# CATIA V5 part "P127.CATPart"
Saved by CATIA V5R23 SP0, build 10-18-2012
Part number: P127
Definition: Axe Tendeur
Bounding box of the stored display mesh (mm): x 0 to 20, y -4 to 4, z -4 to 4
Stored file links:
  C:\wamp\www\COURS\CONCEPTION GMP1\TITRE 02-SEMESTRE 2\03-TP7-PRESSE MECANIQUE\eleve\P127.CATPart
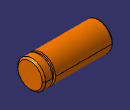
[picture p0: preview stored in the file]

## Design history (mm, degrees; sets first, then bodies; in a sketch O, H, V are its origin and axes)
Body1 (main body)
  Sketch1 on yz-plane, origin (0, 0, 0), H (0, 1, 0), V (0, 0, 1)
    circle A1 centre (0, 0) radius 4
    radius A1 = 4
  Pad1: profile Sketch1, direction (1, 0, 0), length 20
  Chamfer1: length 0.5, angle 45, on edge [face of Pad1 | face of Pad1]
  Thread1: "M8", diameter 8, depth 5, pitch 1.25, on face of Pad1, from face of Pad1
  Chamfer2: length 0.5, angle 45, on edge [face of Pad1 | face of Pad1]
  Sketch2 on zx-plane, origin (0, 0, 0), H (-1, 0, 0), V (0, 0, 1)
    line L1 (-17.5, 7.0809) -> (-16.7, 7.0809)
    line L2 (-16.7, 7.0809) -> (-16.7, 3.5)
    line L3 (-16.7, 3.5) -> (-17.5, 3.5)
    line L4 (-17.5, 3.5) -> (-17.5, 7.0809)
    reference projected line E1 (-20, -3.5) -> (-20, 3.5) from edge [face of Chamfer2 | face of Pad1]
    length L1 = 0.8
    distance H L3 = 3.5
    distance L4 E1 = 2.5
    horizontal: L1 H, L3 H
    vertical: L2 V, L4 V
  Groove1: profile Sketch2, axis Sketch2.H, angle 360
